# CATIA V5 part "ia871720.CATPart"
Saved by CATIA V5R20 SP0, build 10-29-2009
Part number: IA 871720
Revision: ANY
Definition: UNKNOWN
Nomenclature: IA 871720
Source: Unknown
Bounding box of the stored display mesh (mm): x -4.35 to 4.35, y -17 to 0, z -4.35 to 4.35
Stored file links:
  C:\Users\Utente\Desktop\IO LAVORO\3D X SITO CF\CUMSA\3D files IA\IA 871720\ia871720.CATPart
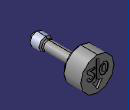
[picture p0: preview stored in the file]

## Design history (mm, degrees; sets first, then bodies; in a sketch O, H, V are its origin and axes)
Body1 "Cortar-Extruir3" (main body)
  Solid1: solid without history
